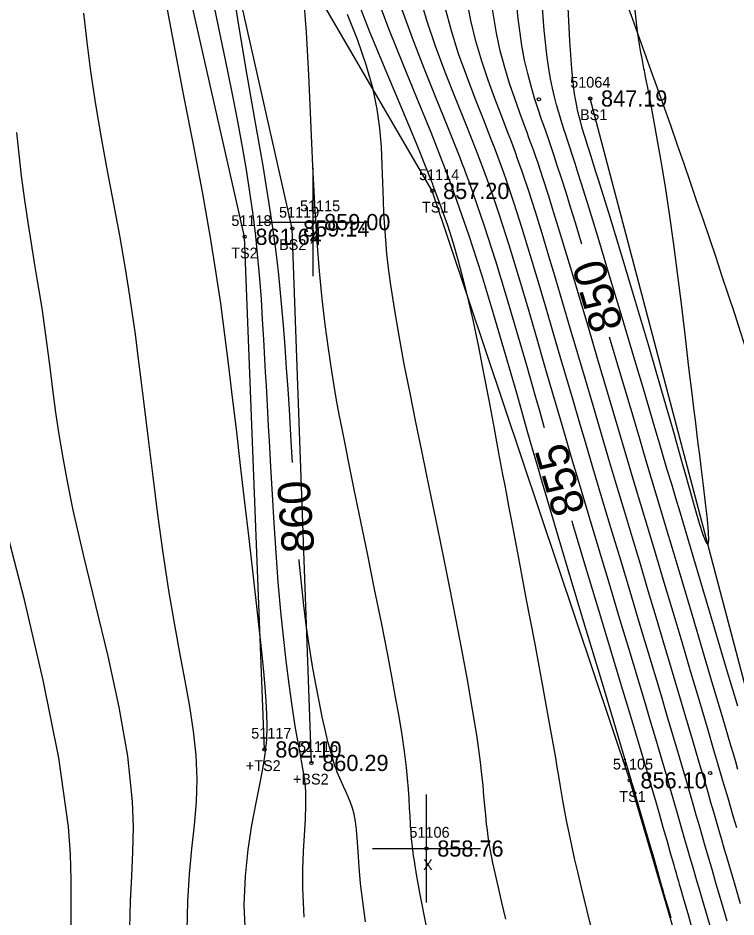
# Model space of a CAD drawing. Extents: x 1378535 to 1380697, y 997729 to 1000024.
# Drawn here: x 1380464.6 to 1380531, y 997912.8 to 997996 of the extents above; entities that cross this region are included whole.
import ezdxf

# ---------------------------------------------------------------- set-up
doc = ezdxf.new("R2010")
doc.units = 0
for name, color, linetype in [('RD_DTM_BkLn1', 7, 'Continuous'), ('RD_DTM_BkLn2', 7, 'Continuous'), ('RD_DTM_BkLn_txCode', 7, 'Continuous'), ('RD_DTM_Major1', 7, 'Continuous'), ('RD_DTM_Major1_Lbl', 7, 'Continuous'), ('RD_DTM_Minor1', 7, 'Continuous'), ('RD_EX_Misc', 7, 'Continuous'), ('RD_EX_Misc_txCode', 7, 'Continuous'), ('RD_EX_Road', 7, 'Continuous'), ('RD_EX_TX_Misc_ELEV', 7, 'Continuous'), ('RD_SMD_Locator', 7, 'Continuous')]:
    doc.layers.add(name, color=color, linetype=linetype)

msp = doc.modelspace()

# ---------------------------------------------------------------- linework, layer by layer
at = {"layer": 'RD_DTM_BkLn1'}
msp.add_spline([(1380561.34, 997899.221), (1380543.703, 997960.783), (1380525.014, 998016.596), (1380501.317, 998075.31), (1380476.746, 998129.121), (1380448.822, 998181.196), (1380418.354, 998233.119), (1380383.215, 998285.146), (1380349.465, 998331.418), (1380310.818, 998378.028), (1380271.622, 998420.471), (1380231.531, 998459.847)], degree=3, dxfattribs=at)
at = {"layer": 'RD_DTM_BkLn2'}
for points in [[(1380487.363, 997928.335), (1380485.527, 997975.791), (1380475.579, 998019.723)], [(1380491.711, 997927.088), (1380489.94, 997976.566), (1380480.452, 998018.575)], [(1380566.757, 997751.771), (1380557.077, 997803.811), (1380541.168, 997857.405), (1380521.16, 997925.477), (1380502.894, 997980.039), (1380480.452, 998018.575)], [(1380574.915, 997757.623), (1380570.09, 997784.156), (1380563.954, 997811.43), (1380563.127, 997815.458), (1380562.818, 997818.699), (1380551.354, 997861.143), (1380533.627, 997927.476), (1380517.511, 997988.596)]]:
    msp.add_lwpolyline(points, dxfattribs=at)
at = {"layer": 'RD_DTM_Major1'}
for points in [[(1380489.947, 997954.894), (1380489.892, 997955.861), (1380489.832, 997956.913), (1380489.771, 997957.981), (1380489.663, 997959.81), (1380489.545, 997961.7), (1380489.415, 997963.639), (1380489.272, 997965.615), (1380489.114, 997967.615), (1380488.939, 997969.629), (1380488.815, 997970.934), (1380488.679, 997972.263), (1380488.523, 997973.638), (1380488.344, 997975.083), (1380488.136, 997976.619), (1380487.893, 997978.272), (1380487.229, 997982.364), (1380486.453, 997986.858), (1380485.648, 997991.479), (1380484.897, 997995.952), (1380484.283, 998000.001)], [(1380516.73, 997975.119), (1380516.612, 997975.513), (1380516.135, 997977.081), (1380515.689, 997978.534), (1380515.269, 997979.881), (1380514.873, 997981.134), (1380514.495, 997982.301), (1380514.133, 997983.393), (1380513.944, 997983.95), (1380513.758, 997984.495), (1380513.573, 997985.031), (1380513.388, 997985.564), (1380513.202, 997986.099), (1380513.015, 997986.643), (1380512.685, 997987.616), (1380512.355, 997988.641), (1380512.032, 997989.729), (1380511.725, 997990.895), (1380511.44, 997992.149), (1380511.187, 997993.504), (1380510.84, 997996.004), (1380510.558, 997998.732)], [(1380513.287, 997958.118), (1380513.261, 997958.208), (1380512.876, 997959.543), (1380512.484, 997960.909), (1380511.635, 997963.88), (1380510.729, 997967.018), (1380509.772, 997970.256), (1380508.771, 997973.529), (1380507.729, 997976.769), (1380506.653, 997979.909), (1380506.46, 997980.448), (1380506.266, 997980.982), (1380506.07, 997981.514), (1380505.872, 997982.044), (1380505.672, 997982.572), (1380505.469, 997983.102), (1380504.368, 997985.886), (1380503.233, 997988.678), (1380502.112, 997991.45), (1380501.055, 997994.172), (1380500.109, 997996.815)], [(1380531.18, 997926.491), (1380530.973, 997927.197), (1380530.757, 997927.932), (1380530.529, 997928.705), (1380529.746, 997931.358), (1380528.87, 997934.319), (1380527.932, 997937.477), (1380526.969, 997940.721), (1380526.012, 997943.937), (1380525.095, 997947.015), (1380524.579, 997948.745), (1380524.081, 997950.415), (1380523.592, 997952.056), (1380522.606, 997955.369), (1380522.092, 997957.1), (1380521.196, 997960.12), (1380520.258, 997963.287), (1380519.307, 997966.496)], [(1380478.433, 997856.897), (1380477.241, 997862.311), (1380475.332, 997871.263), (1380473.421, 997880.787), (1380471.702, 997890.275), (1380470.368, 997899.121), (1380469.613, 997906.721), (1380469.506, 997909.334), (1380469.478, 997911.738), (1380469.484, 997914.027), (1380469.475, 997916.298), (1380469.404, 997918.647), (1380469.224, 997921.167), (1380468.327, 997927.566), (1380466.891, 997934.748), (1380465.14, 997942.187), (1380463.3, 997949.354), (1380461.728, 997955.227)], [(1380526.889, 997911.977), (1380526.623, 997912.903), (1380526.142, 997914.574), (1380525.921, 997915.344), (1380525.81, 997915.73), (1380525.701, 997916.111), (1380525.592, 997916.489), (1380525.484, 997916.867), (1380525.375, 997917.247), (1380525.266, 997917.63), (1380524.947, 997918.747), (1380524.615, 997919.911), (1380524.27, 997921.121), (1380523.911, 997922.374), (1380523.538, 997923.669), (1380523.151, 997925.005), (1380522.89, 997925.898), (1380522.62, 997926.818), (1380522.337, 997927.776), (1380522.038, 997928.784), (1380521.72, 997929.852), (1380521.38, 997930.991), (1380520.411, 997934.221), (1380519.328, 997937.82), (1380518.182, 997941.627), (1380517.023, 997945.482), (1380515.903, 997949.225), (1380515.826, 997949.483)], [(1380496.709, 997912.369), (1380496.451, 997914.256), (1380496.256, 997915.94), (1380496.119, 997917.451), (1380496.054, 997918.415), (1380496.003, 997919.313), (1380495.952, 997920.15), (1380495.888, 997920.93), (1380495.798, 997921.657), (1380495.668, 997922.334), (1380495.514, 997922.895), (1380495.327, 997923.427), (1380495.118, 997923.936), (1380494.896, 997924.43), (1380494.67, 997924.914), (1380494.449, 997925.396), (1380494.329, 997925.672), (1380494.214, 997925.951), (1380494.102, 997926.235), (1380493.993, 997926.526), (1380493.887, 997926.825), (1380493.784, 997927.134), (1380493.654, 997927.551), (1380493.525, 997927.99), (1380493.398, 997928.454), (1380493.27, 997928.947), (1380493.141, 997929.471), (1380493.009, 997930.029), (1380492.716, 997931.341), (1380492.413, 997932.799), (1380492.108, 997934.379), (1380491.809, 997936.059), (1380491.525, 997937.817), (1380491.262, 997939.631), (1380491.005, 997941.666), (1380490.781, 997943.716), (1380490.587, 997945.757), (1380490.573, 997945.916)]]:
    msp.add_lwpolyline(points, dxfattribs=at)
at = {"layer": 'RD_DTM_Minor1'}
for points in [[(1380502.403, 997911.778), (1380501.755, 997915.065), (1380501.621, 997915.778), (1380501.503, 997916.424), (1380501.399, 997917.012), (1380501.309, 997917.547), (1380501.232, 997918.035), (1380501.166, 997918.483), (1380501.127, 997918.774), (1380501.091, 997919.051), (1380501.06, 997919.317), (1380501.031, 997919.575), (1380501.005, 997919.827), (1380500.981, 997920.076), (1380500.961, 997920.296), (1380500.942, 997920.517), (1380500.924, 997920.741), (1380500.906, 997920.969), (1380500.89, 997921.203), (1380500.874, 997921.445), (1380500.834, 997922.146), (1380500.794, 997922.914), (1380500.747, 997923.75), (1380500.686, 997924.655), (1380500.607, 997925.63), (1380500.502, 997926.676), (1380500.322, 997928.13), (1380500.093, 997929.701), (1380499.818, 997931.387), (1380499.503, 997933.184), (1380499.151, 997935.09), (1380498.766, 997937.103), (1380498.18, 997940.082), (1380497.558, 997943.182), (1380496.919, 997946.322), (1380496.285, 997949.421), (1380495.675, 997952.397), (1380495.111, 997955.169), (1380494.817, 997956.625), (1380494.543, 997958.012), (1380494.285, 997959.354), (1380494.042, 997960.675), (1380493.811, 997961.997), (1380493.59, 997963.345), (1380493.275, 997965.45), (1380492.981, 997967.683), (1380492.708, 997970.062), (1380492.461, 997972.608), (1380492.24, 997975.338), (1380492.048, 997978.273), (1380491.841, 997982.341), (1380491.657, 997986.578), (1380491.469, 997990.781), (1380491.248, 997994.746), (1380490.966, 997998.272)], [(1380517.851, 997910.895), (1380517.23, 997913.402), (1380516.673, 997915.687), (1380516.357, 997917.008), (1380516.066, 997918.254), (1380515.799, 997919.447), (1380515.551, 997920.608), (1380515.32, 997921.758), (1380515.102, 997922.921), (1380514.978, 997923.623), (1380514.854, 997924.344), (1380514.729, 997925.091), (1380514.599, 997925.873), (1380514.462, 997926.697), (1380514.315, 997927.57), (1380513.753, 997930.765), (1380513.092, 997934.385), (1380512.37, 997938.255), (1380511.624, 997942.199), (1380510.894, 997946.044), (1380510.217, 997949.614), (1380510.012, 997950.7), (1380509.815, 997951.749), (1380509.624, 997952.769), (1380509.437, 997953.772), (1380509.251, 997954.768), (1380509.066, 997955.767), (1380508.614, 997958.206), (1380508.151, 997960.684), (1380507.677, 997963.162), (1380507.19, 997965.603), (1380506.693, 997967.966), (1380506.183, 997970.214), (1380505.765, 997971.911), (1380505.325, 997973.551), (1380504.848, 997975.174), (1380504.319, 997976.823), (1380503.723, 997978.537), (1380503.046, 997980.358), (1380502.989, 997980.506), (1380502.932, 997980.654), (1380502.874, 997980.804), (1380502.815, 997980.955), (1380502.756, 997981.106), (1380502.697, 997981.259), (1380501.422, 997984.421), (1380500.005, 997987.827), (1380498.534, 997991.345), (1380497.097, 997994.843), (1380495.783, 997998.189)], [(1380528.662, 997911.786), (1380527.9, 997914.403), (1380527.556, 997915.585), (1380527.386, 997916.168), (1380527.221, 997916.736), (1380527.06, 997917.293), (1380526.741, 997918.396), (1380526.581, 997918.95), (1380526.279, 997920.003), (1380525.968, 997921.086), (1380525.648, 997922.201), (1380525.318, 997923.35), (1380524.976, 997924.535), (1380524.621, 997925.759), (1380524.261, 997926.994), (1380523.883, 997928.28), (1380523.484, 997929.63), (1380523.061, 997931.055), (1380522.61, 997932.569), (1380522.128, 997934.183), (1380521.229, 997937.179), (1380520.26, 997940.403), (1380519.252, 997943.754), (1380518.238, 997947.13), (1380517.25, 997950.431), (1380516.32, 997953.555), (1380515.784, 997955.365), (1380515.274, 997957.096), (1380514.781, 997958.779), (1380514.297, 997960.44), (1380513.813, 997962.11), (1380513.32, 997963.816), (1380512.539, 997966.52), (1380511.724, 997969.322), (1380510.878, 997972.168), (1380510.007, 997975.007), (1380509.115, 997977.786), (1380508.208, 997980.452), (1380507.999, 997981.039), (1380507.79, 997981.619), (1380507.578, 997982.194), (1380507.364, 997982.767), (1380507.147, 997983.339), (1380506.927, 997983.912), (1380505.997, 997986.258), (1380505.038, 997988.64), (1380504.089, 997991.039), (1380503.191, 997993.44), (1380502.382, 997995.827), (1380501.705, 997998.184)], [(1380531.418, 997914.052), (1380530.788, 997916.197), (1380530.49, 997917.212), (1380530.21, 997918.17), (1380529.943, 997919.083), (1380529.687, 997919.96), (1380529.439, 997920.813), (1380529.195, 997921.652), (1380528.937, 997922.541), (1380528.677, 997923.438), (1380528.411, 997924.354), (1380528.136, 997925.301), (1380527.849, 997926.291), (1380527.544, 997927.333), (1380526.983, 997929.245), (1380526.373, 997931.315), (1380525.722, 997933.513), (1380525.04, 997935.811), (1380524.334, 997938.178), (1380523.615, 997940.587), (1380522.885, 997943.026), (1380522.151, 997945.473), (1380521.416, 997947.928), (1380520.68, 997950.386), (1380519.945, 997952.845), (1380519.213, 997955.302), (1380518.489, 997957.742), (1380517.77, 997960.17), (1380517.059, 997962.582), (1380516.355, 997964.971), (1380515.661, 997967.331), (1380514.976, 997969.656), (1380514.326, 997971.86), (1380513.686, 997974.012), (1380513.055, 997976.098), (1380512.433, 997978.105), (1380511.818, 997980.02), (1380511.209, 997981.829), (1380511, 997982.429), (1380510.79, 997983.018), (1380510.579, 997983.601), (1380510.365, 997984.18), (1380510.148, 997984.759), (1380509.927, 997985.342), (1380509.314, 997986.933), (1380508.684, 997988.581), (1380508.062, 997990.291), (1380507.468, 997992.066), (1380506.926, 997993.911), (1380506.459, 997995.829), (1380506.036, 997998.088)], [(1380525, 997912.706), (1380524.742, 997913.602), (1380524.488, 997914.479), (1380524.448, 997914.618), (1380524.408, 997914.757), (1380524.367, 997914.897), (1380524.327, 997915.037), (1380524.286, 997915.179), (1380524.245, 997915.321), (1380524.224, 997915.395), (1380524.202, 997915.469), (1380524.181, 997915.544), (1380524.137, 997915.694), (1380524.116, 997915.769), (1380523.763, 997917), (1380523.381, 997918.335), (1380522.966, 997919.785), (1380522.514, 997921.36), (1380522.019, 997923.068), (1380521.478, 997924.919), (1380521.372, 997925.279), (1380521.264, 997925.644), (1380521.155, 997926.016), (1380520.929, 997926.777), (1380520.814, 997927.168), (1380519.694, 997930.919), (1380518.45, 997935.059), (1380517.138, 997939.415), (1380515.815, 997943.817), (1380514.538, 997948.092), (1380513.362, 997952.071), (1380513.068, 997953.073), (1380512.784, 997954.05), (1380512.506, 997955.01), (1380512.232, 997955.961), (1380511.959, 997956.913), (1380511.684, 997957.873), (1380510.707, 997961.304), (1380509.68, 997964.884), (1380508.601, 997968.557), (1380507.466, 997972.268), (1380506.274, 997975.961), (1380505.022, 997979.581), (1380504.864, 997980.017), (1380504.705, 997980.452), (1380504.546, 997980.885), (1380504.384, 997981.317), (1380504.222, 997981.749), (1380504.057, 997982.181), (1380502.777, 997985.437), (1380501.459, 997988.67), (1380500.16, 997991.836), (1380498.936, 997994.891), (1380497.846, 997997.79)], [(1380531.066, 997921.07), (1380530.775, 997922.065), (1380530.491, 997923.038), (1380530.262, 997923.822), (1380530.032, 997924.613), (1380529.796, 997925.421), (1380529.295, 997927.135), (1380529.024, 997928.062), (1380528.356, 997930.33), (1380527.617, 997932.831), (1380526.827, 997935.498), (1380526.006, 997938.26), (1380525.175, 997941.052), (1380524.354, 997943.803), (1380523.727, 997945.903), (1380523.112, 997947.959), (1380522.503, 997949.993), (1380521.896, 997952.028), (1380521.282, 997954.085), (1380520.656, 997956.189), (1380519.847, 997958.916), (1380519.021, 997961.706), (1380518.191, 997964.513), (1380517.369, 997967.292), (1380516.567, 997969.998), (1380515.797, 997972.587), (1380515.226, 997974.495), (1380514.68, 997976.305), (1380514.155, 997978.02), (1380513.648, 997979.639), (1380513.157, 997981.164), (1380512.678, 997982.597), (1380512.477, 997983.18), (1380512.276, 997983.751), (1380512.076, 997984.314), (1380511.873, 997984.874), (1380511.668, 997985.434), (1380511.46, 997986.001), (1380510.992, 997987.267), (1380510.517, 997988.591), (1380510.048, 997989.982), (1380509.6, 997991.45), (1380509.189, 997993.005), (1380508.828, 997994.658), (1380508.434, 997997.058)], [(1380531.155, 997932.331), (1380530.127, 997935.799), (1380529.038, 997939.465), (1380527.929, 997943.194), (1380526.842, 997946.849), (1380525.818, 997950.294), (1380525.427, 997951.607), (1380525.048, 997952.883), (1380524.674, 997954.141), (1380524.3, 997955.401), (1380523.919, 997956.682), (1380523.527, 997958.005), (1380522.522, 997961.395), (1380521.456, 997964.987), (1380520.371, 997968.636), (1380519.307, 997972.191), (1380518.308, 997975.507), (1380517.413, 997978.435), (1380517.05, 997979.608), (1380516.713, 997980.681), (1380516.402, 997981.664), (1380516.112, 997982.569), (1380515.841, 997983.408), (1380515.585, 997984.191), (1380515.41, 997984.725), (1380515.24, 997985.243), (1380515.075, 997985.752), (1380514.914, 997986.258), (1380514.756, 997986.769), (1380514.6, 997987.291), (1380514.4, 997988), (1380514.204, 997988.75), (1380514.016, 997989.553), (1380513.838, 997990.418), (1380513.672, 997991.358), (1380513.523, 997992.382), (1380513.251, 997994.934), (1380513.019, 997997.832)], [(1380521.533, 997997.64), (1380521.791, 997995.333), (1380521.885, 997994.625), (1380521.978, 997993.987), (1380522.074, 997993.399), (1380522.172, 997992.841), (1380522.274, 997992.293), (1380522.382, 997991.736), (1380522.417, 997991.557), (1380522.453, 997991.376), (1380522.489, 997991.191), (1380522.527, 997991.001), (1380522.565, 997990.808), (1380522.604, 997990.61), (1380522.919, 997988.99), (1380523.271, 997987.127), (1380523.648, 997985.055), (1380524.039, 997982.807), (1380524.433, 997980.418), (1380524.817, 997977.92), (1380525.217, 997975.091), (1380525.594, 997972.213), (1380525.951, 997969.329), (1380526.292, 997966.479), (1380526.619, 997963.707), (1380526.935, 997961.052), (1380527.073, 997959.915), (1380527.209, 997958.805), (1380527.345, 997957.714), (1380527.48, 997956.638), (1380527.614, 997955.569), (1380527.748, 997954.504), (1380527.963, 997952.768), (1380528.16, 997951.119), (1380528.32, 997949.656), (1380528.423, 997948.473), (1380528.453, 997947.669), (1380528.389, 997947.34), (1380528.228, 997947.538), (1380527.973, 997948.201), (1380527.636, 997949.262), (1380527.227, 997950.655), (1380526.758, 997952.312), (1380526.238, 997954.166), (1380526.09, 997954.694), (1380525.939, 997955.232), (1380525.784, 997955.78), (1380525.626, 997956.338), (1380525.465, 997956.907), (1380525.3, 997957.487), (1380524.141, 997961.509), (1380522.888, 997965.788), (1380521.607, 997970.108), (1380520.362, 997974.253), (1380519.221, 997978.008), (1380518.247, 997981.156), (1380518.012, 997981.906), (1380517.795, 997982.596), (1380517.593, 997983.233), (1380517.406, 997983.824), (1380517.233, 997984.373), (1380517.073, 997984.888), (1380516.9, 997985.451), (1380516.742, 997985.985), (1380516.597, 997986.504), (1380516.464, 997987.019), (1380516.341, 997987.539), (1380516.229, 997988.078), (1380516.142, 997988.543), (1380516.062, 997989.033), (1380515.988, 997989.553), (1380515.919, 997990.109), (1380515.856, 997990.707), (1380515.799, 997991.351), (1380515.635, 997993.923), (1380515.478, 997996.979)], [(1380480.222, 997911.555), (1380480.264, 997914.274), (1380480.426, 997916.781), (1380480.652, 997919.121), (1380480.884, 997921.34), (1380481.064, 997923.482), (1380481.133, 997925.591), (1380481.044, 997927.795), (1380480.807, 997930.033), (1380480.459, 997932.322), (1380480.032, 997934.681), (1380479.563, 997937.132), (1380479.087, 997939.691), (1380478.522, 997943.049), (1380477.996, 997946.536), (1380477.506, 997950.081), (1380477.049, 997953.611), (1380476.623, 997957.056), (1380476.225, 997960.344), (1380475.955, 997962.564), (1380475.688, 997964.699), (1380475.416, 997966.782), (1380475.128, 997968.844), (1380474.816, 997970.917), (1380474.471, 997973.033), (1380473.963, 997975.897), (1380473.409, 997978.859), (1380472.837, 997981.889), (1380472.275, 997984.957), (1380471.749, 997988.035), (1380471.288, 997991.091), (1380470.942, 997993.816), (1380470.648, 997996.498)], [(1380485.658, 997909.815), (1380485.495, 997913.947), (1380485.602, 997916.598), (1380485.853, 997919.058), (1380486.196, 997921.322), (1380486.581, 997923.383), (1380486.955, 997925.234), (1380487.268, 997926.869), (1380487.306, 997927.087), (1380487.34, 997927.3), (1380487.373, 997927.51), (1380487.403, 997927.716), (1380487.431, 997927.918), (1380487.457, 997928.118), (1380487.502, 997928.518), (1380487.539, 997928.911), (1380487.567, 997929.299), (1380487.587, 997929.687), (1380487.601, 997930.077), (1380487.607, 997930.473), (1380487.591, 997931.6), (1380487.533, 997932.81), (1380487.436, 997934.118), (1380487.305, 997935.54), (1380487.144, 997937.091), (1380486.959, 997938.788), (1380486.648, 997941.561), (1380486.303, 997944.606), (1380485.931, 997947.848), (1380485.544, 997951.207), (1380485.151, 997954.609), (1380484.761, 997957.976), (1380484.418, 997960.924), (1380484.071, 997963.821), (1380483.707, 997966.709), (1380483.311, 997969.627), (1380482.87, 997972.617), (1380482.369, 997975.717), (1380481.615, 997979.961), (1380480.787, 997984.329), (1380479.937, 997988.688), (1380479.116, 997992.903), (1380478.376, 997996.841)], [(1380491.045, 997912.808), (1380490.897, 997915.514), (1380490.902, 997917.251), (1380490.969, 997918.877), (1380491.063, 997920.403), (1380491.152, 997921.839), (1380491.2, 997923.195), (1380491.175, 997924.48), (1380491.117, 997925.186), (1380491.03, 997925.883), (1380490.92, 997926.582), (1380490.792, 997927.294), (1380490.653, 997928.028), (1380490.508, 997928.797), (1380490.211, 997930.499), (1380489.919, 997932.368), (1380489.635, 997934.384), (1380489.364, 997936.527), (1380489.11, 997938.777), (1380488.877, 997941.113), (1380488.644, 997943.81), (1380488.439, 997946.543), (1380488.257, 997949.267), (1380488.096, 997951.933), (1380487.951, 997954.494), (1380487.819, 997956.902), (1380487.745, 997958.252), (1380487.673, 997959.546), (1380487.604, 997960.801), (1380487.535, 997962.034), (1380487.467, 997963.259), (1380487.399, 997964.493), (1380487.301, 997966.286), (1380487.194, 997968.124), (1380487.072, 997970.004), (1380486.929, 997971.922), (1380486.758, 997973.872), (1380486.552, 997975.851), (1380486.304, 997977.866), (1380486.016, 997979.911), (1380485.69, 997981.994), (1380485.326, 997984.121), (1380484.927, 997986.298), (1380484.493, 997988.533), (1380483.932, 997991.293), (1380483.346, 997994.095), (1380482.756, 997996.888)], [(1380509.696, 997912.623), (1380509.327, 997914.174), (1380509.007, 997915.541), (1380508.732, 997916.755), (1380508.499, 997917.845), (1380508.372, 997918.485), (1380508.259, 997919.097), (1380508.158, 997919.691), (1380508.068, 997920.277), (1380507.988, 997920.863), (1380507.917, 997921.459), (1380507.834, 997922.268), (1380507.756, 997923.12), (1380507.676, 997924.024), (1380507.587, 997924.99), (1380507.481, 997926.028), (1380507.351, 997927.148), (1380507.031, 997929.465), (1380506.622, 997932.028), (1380506.146, 997934.764), (1380505.623, 997937.602), (1380505.073, 997940.469), (1380504.516, 997943.293), (1380504.081, 997945.466), (1380503.652, 997947.587), (1380503.225, 997949.677), (1380502.797, 997951.757), (1380502.365, 997953.846), (1380501.927, 997955.965), (1380501.378, 997958.626), (1380500.831, 997961.319), (1380500.304, 997964), (1380499.816, 997966.625), (1380499.383, 997969.148), (1380499.023, 997971.526), (1380498.846, 997972.892), (1380498.7, 997974.202), (1380498.582, 997975.47), (1380498.49, 997976.712), (1380498.419, 997977.942), (1380498.367, 997979.175), (1380498.32, 997980.787), (1380498.268, 997982.433), (1380498.183, 997984.117), (1380498.033, 997985.844), (1380497.787, 997987.619), (1380497.417, 997989.445), (1380496.775, 997991.724), (1380495.966, 997994.043), (1380495.052, 997996.357)], [(1380530.181, 997912.443), (1380529.66, 997914.225), (1380529.178, 997915.87), (1380528.946, 997916.664), (1380528.723, 997917.426), (1380528.509, 997918.162), (1380528.095, 997919.587), (1380527.891, 997920.29), (1380527.608, 997921.27), (1380527.321, 997922.265), (1380527.028, 997923.283), (1380526.409, 997925.422), (1380526.078, 997926.56), (1380525.619, 997928.13), (1380525.129, 997929.794), (1380524.609, 997931.553), (1380524.06, 997933.403), (1380523.481, 997935.345), (1380522.874, 997937.376), (1380522.053, 997940.114), (1380521.201, 997942.954), (1380520.331, 997945.851), (1380519.459, 997948.759), (1380518.599, 997951.633), (1380517.766, 997954.428), (1380517.132, 997956.564), (1380516.519, 997958.641), (1380515.92, 997960.677), (1380514.742, 997964.702), (1380514.151, 997966.729), (1380513.433, 997969.193), (1380512.704, 997971.673), (1380511.966, 997974.137), (1380511.222, 997976.552), (1380510.473, 997978.886), (1380509.722, 997981.106), (1380509.509, 997981.71), (1380509.295, 997982.304), (1380509.08, 997982.893), (1380508.862, 997983.478), (1380508.641, 997984.063), (1380508.415, 997984.651), (1380507.648, 997986.601), (1380506.858, 997988.601), (1380506.075, 997990.647), (1380505.33, 997992.733), (1380504.656, 997994.855), (1380504.083, 997997.007)], [(1380474.893, 997911.822), (1380474.964, 997914.277), (1380475.08, 997916.594), (1380475.187, 997918.851), (1380475.231, 997921.129), (1380475.158, 997923.505), (1380474.703, 997927.722), (1380473.907, 997932.258), (1380472.888, 997936.956), (1380471.764, 997941.661), (1380470.651, 997946.218), (1380469.668, 997950.472), (1380469.151, 997952.987), (1380468.722, 997955.326), (1380468.365, 997957.502), (1380468.067, 997959.529), (1380467.811, 997961.42), (1380467.584, 997963.19), (1380467.431, 997964.388), (1380467.281, 997965.547), (1380467.13, 997966.684), (1380466.973, 997967.814), (1380466.807, 997968.954), (1380466.627, 997970.12), (1380466.368, 997971.705), (1380466.086, 997973.384), (1380465.79, 997975.175), (1380465.486, 997977.101), (1380465.183, 997979.182), (1380464.888, 997981.439), (1380464.44, 997985.447)]]:
    msp.add_lwpolyline(points, dxfattribs=at)
at = {"layer": 'RD_EX_Misc'}
for p, q in [((1380491.88, 997972.153), (1380491.88, 997982.153)), ((1380486.88, 997977.153), (1380496.88, 997977.153)), ((1380502.352, 997914.163), (1380502.352, 997924.163)), ((1380497.352, 997919.163), (1380507.352, 997919.163))]:
    msp.add_line(p, q, dxfattribs=at)
at = {"layer": 'RD_EX_Road'}
for points in [[(1380571.276, 997900.848), (1380553.838, 997963.229), (1380535.074, 998018.791), (1380510.809, 998079.184), (1380486.363, 998133.158), (1380458.393, 998185.941), (1380428.109, 998238.221), (1380392.689, 998291.143), (1380357.52, 998337.623), (1380319.367, 998385.164), (1380279.255, 998428.684), (1380239.596, 998468.129), (1380183.367, 998518.832)], [(1380551.892, 997897.33), (1380534.244, 997958.196), (1380514.831, 998013.467), (1380491.083, 998070.746), (1380467.518, 998124.397), (1380439.882, 998176.529), (1380409.174, 998228.123), (1380375.886, 998278.447), (1380340.748, 998326.222), (1380303.332, 998371.138), (1380263.981, 998413.97), (1380224.662, 998452.644), (1380168.713, 998504.787)]]:
    msp.add_spline(points, degree=3, dxfattribs=at)
at = {"layer": 'RD_SMD_Locator'}
for centre in [(1380517.511, 997988.596), (1380512.757, 997988.518), (1380502.894, 997980.039), (1380491.88, 997977.153), (1380489.94, 997976.566), (1380485.527, 997975.791), (1380487.363, 997928.335), (1380491.711, 997927.088), (1380521.16, 997925.477), (1380528.6, 997926.15), (1380502.352, 997919.163)]:
    msp.add_circle(centre, 0.15, dxfattribs=at)

# ---------------------------------------------------------------- texts
at = {"layer": 'RD_DTM_BkLn_txCode'}
for s, p in [('51064', (1380515.653, 997989.596)), ('BS1', (1380516.566, 997986.596)), ('51114', (1380501.666, 997981.039)), ('TS1', (1380501.933, 997978.039)), ('51119', (1380488.712, 997977.566)), ('51118', (1380484.299, 997976.791)), ('BS2', (1380488.712, 997974.566)), ('TS2', (1380484.283, 997973.791)), ('51117', (1380486.135, 997929.335)), ('51116', (1380490.459, 997928.088)), ('+TS2', (1380485.631, 997926.335)), ('51105', (1380519.609, 997926.477)), ('+BS2', (1380489.994, 997925.088)), ('TS1', (1380520.199, 997923.477))]:
    msp.add_text(s, height=1, dxfattribs=at).set_placement(p)
at = {"layer": 'RD_DTM_Major1_Lbl'}
for s, rotation, p in [('850', 106.63828, (1380520.577, 997967.504)), ('855', 106.38624, (1380517.086, 997950.481)), ('860', 93.98952, (1380491.992, 997946.643))]:
    msp.add_text(s, height=3, rotation=rotation, dxfattribs=at).set_placement(p)
at = {"layer": 'RD_EX_Misc_txCode'}
for s, p in [('51115', (1380490.652, 997978.153)), ('X', (1380491.565, 997975.153)), ('51106', (1380500.777, 997920.163)), ('X', (1380502.037, 997917.163))]:
    msp.add_text(s, height=1, dxfattribs=at).set_placement(p)
at = {"layer": 'RD_EX_TX_Misc_ELEV'}
for s, p in [('847.19', (1380518.511, 997987.846)), ('857.20', (1380503.894, 997979.289)), ('859.00', (1380492.88, 997976.403)), ('859.14', (1380490.94, 997975.816)), ('861.64', (1380486.527, 997975.041)), ('862.10', (1380488.363, 997927.585)), ('860.29', (1380492.711, 997926.338)), ('856.10', (1380522.16, 997924.727)), ('858.76', (1380503.352, 997918.413))]:
    msp.add_text(s, height=1.5, dxfattribs=at).set_placement(p)

doc.saveas('drawing.dxf')
